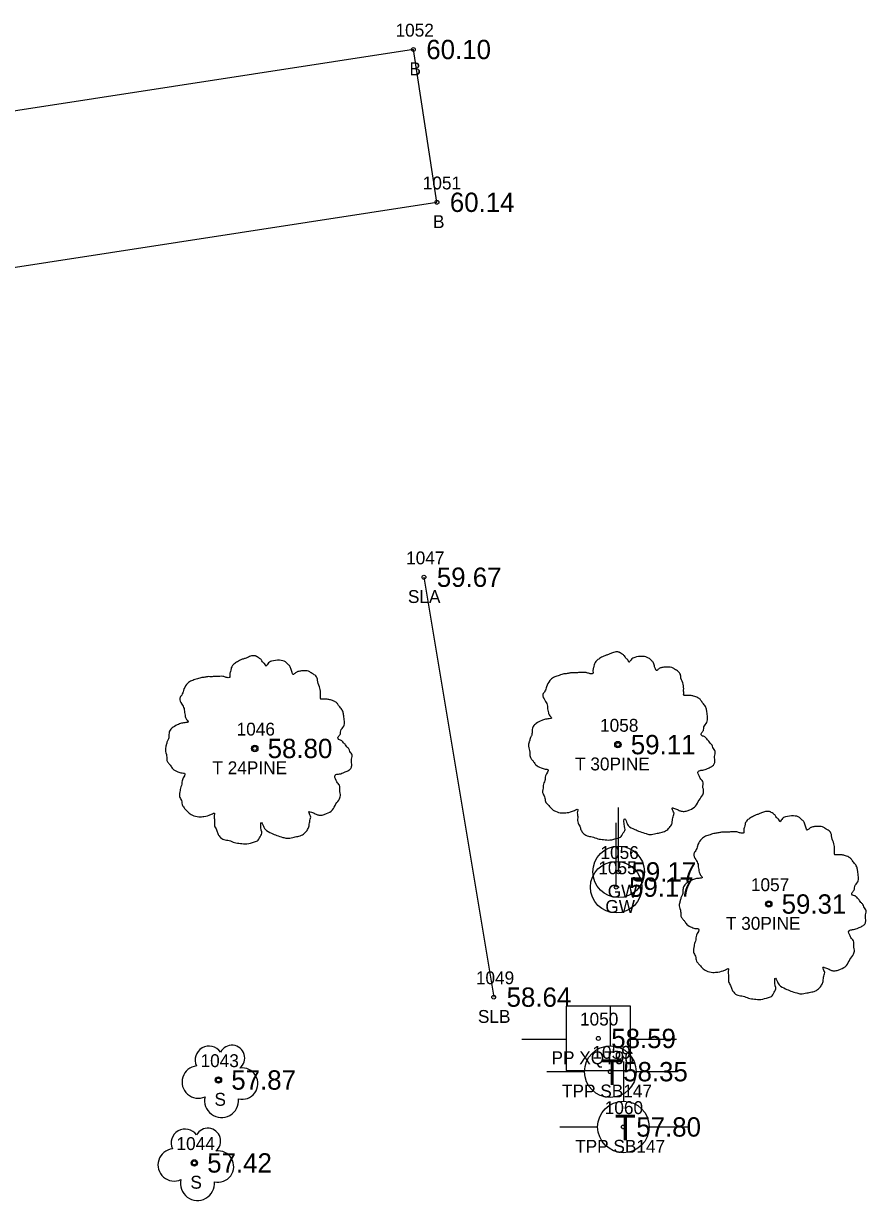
# Model space of a CAD drawing. Extents: x 2420113 to 2422887, y 845323 to 846653.
# Drawn here: x 2420530 to 2420595.4, y 845741.1 to 845832.4 of the extents above; entities that cross this region are included whole.
import ezdxf

# ---------------------------------------------------------------- set-up
doc = ezdxf.new("R2010")
doc.units = 0
for name, color, linetype in [('RD_EX_Bldg', 7, 'Continuous'), ('RD_EX_Bldg_txCode', 7, 'Continuous'), ('RD_EX_TX_Bldg_ELEV', 7, 'Continuous'), ('RD_EX_TX_UT_ELEV', 7, 'Continuous'), ('RD_EX_TX_VEG_ELEV', 7, 'Continuous'), ('RD_EX_UT', 7, 'Continuous'), ('RD_EX_UT_txCode', 7, 'Continuous'), ('RD_EX_VEG', 7, 'Continuous'), ('RD_EX_VEG_txCode', 7, 'Continuous'), ('RD_HC_Survey_ELEV', 7, 'Continuous'), ('RD_SMD_Locator', 7, 'Continuous')]:
    doc.layers.add(name, color=color, linetype=linetype)

msp = doc.modelspace()

# ---------------------------------------------------------------- linework, layer by layer
at = {"layer": 'RD_EX_Bldg'}
msp.add_lwpolyline([(2420506.493, 845809.989), (2420562.053, 845818.556), (2420560.224, 845830.416), (2420504.664, 845821.849), (2420506.493, 845809.989)], dxfattribs=at)
at = {"layer": 'RD_EX_UT'}
for p, q in [((2420576.152, 845766.583), (2420576.152, 845771.583)), ((2420575.962, 845765.398), (2420575.962, 845770.398)), ((2420577.071, 845756.164), (2420572.071, 845756.164)), ((2420572.071, 845756.164), (2420572.071, 845751.164)), ((2420575.504, 845756.144), (2420575.504, 845753.074)), ((2420577.071, 845751.164), (2420577.071, 845756.164)), ((2420568.64, 845753.602), (2420572.109, 845753.602)), ((2420577, 845753.602), (2420580.64, 845753.602)), ((2420576.524, 845751.853), (2420576.524, 845748.783)), ((2420570.574, 845751.089), (2420573.504, 845751.089)), ((2420572.071, 845751.164), (2420577.071, 845751.164)), ((2420577.504, 845751.089), (2420580.574, 845751.089)), ((2420571.594, 845746.798), (2420574.524, 845746.798)), ((2420578.524, 845746.798), (2420581.594, 845746.798))]:
    msp.add_line(p, q, dxfattribs=at)
for centre, radius in [((2420576.152, 845766.583), 1.999), ((2420575.962, 845765.398), 1.999), ((2420575.504, 845751.074), 2), ((2420576.524, 845746.783), 2)]:
    msp.add_circle(centre, radius, dxfattribs=at)
at = {"layer": 'RD_EX_VEG'}
msp.add_line((2420561.044, 845789.453), (2420566.458, 845756.86), dxfattribs=at)
for centre, radius in [((2420547.912, 845776.163), 0.25), ((2420576.097, 845776.46), 0.25), ((2420576.084, 845776.441), 0.0001), ((2420547.899, 845776.144), 0.0001), ((2420587.804, 845764.087), 0.25), ((2420587.792, 845764.068), 0.0001), ((2420545.09, 845750.427), 0.25), ((2420543.222, 845743.991), 0.25)]:
    msp.add_circle(centre, radius, dxfattribs=at)
for centre, radius, start, end in [((2420544.369, 845751.974), 1.084, 34.97629, 204.75602), ((2420546.135, 845752.129), 0.995, 308.76261, 152.04674), ((2420543.526, 845750.271), 1.257, 96.45179, 294.73401), ((2420546.93, 845750.147), 1.218, 256.56668, 98.10463), ((2420545.336, 845748.83), 1.318, 166.88266, 5.75893), ((2420542.501, 845745.538), 1.084, 34.97629, 204.75602), ((2420544.267, 845745.693), 0.995, 308.76261, 152.04674), ((2420541.658, 845743.836), 1.257, 96.45179, 294.73401), ((2420545.061, 845743.712), 1.218, 256.56668, 98.10463), ((2420543.467, 845742.395), 1.318, 166.88266, 5.75893)]:
    msp.add_arc(centre, radius, start, end, dxfattribs=at)
for points in [[(2420576.229, 845783.627), (2420575.929, 845783.652), (2420575.604, 845783.552), (2420575.354, 845783.452), (2420575.129, 845783.377), (2420574.904, 845783.277), (2420574.604, 845783.102), (2420574.379, 845782.902), (2420574.254, 845782.652), (2420574.204, 845782.427), (2420574.154, 845782.152), (2420574.154, 845781.977), (2420574.03, 845781.952), (2420573.88, 845781.977), (2420573.63, 845782.052), (2420573.38, 845782.052), (2420573.13, 845782.052), (2420572.78, 845782.027), (2420572.43, 845782.027), (2420572.155, 845781.977), (2420571.83, 845781.928), (2420571.456, 845781.803), (2420571.106, 845781.678), (2420570.806, 845781.428), (2420570.556, 845780.953), (2420570.431, 845780.603), (2420570.281, 845780.353), (2420570.431, 845779.903), (2420570.606, 845779.554), (2420570.631, 845779.354), (2420570.706, 845778.929), (2420570.806, 845778.704), (2420570.931, 845778.504), (2420570.856, 845778.479), (2420570.481, 845778.429), (2420570.181, 845778.329), (2420569.756, 845778.104), (2420569.531, 845777.879), (2420569.431, 845777.554), (2420569.407, 845777.205), (2420569.307, 845777.005), (2420569.232, 845776.73), (2420569.207, 845776.655), (2420569.157, 845776.33), (2420569.257, 845775.88), (2420569.282, 845775.53), (2420569.407, 845775.305), (2420569.556, 845775.131), (2420569.731, 845774.881), (2420570.131, 845774.656), (2420570.456, 845774.556), (2420570.656, 845774.531), (2420570.481, 845774.031), (2420570.431, 845773.681), (2420570.306, 845773.281), (2420570.306, 845773.206), (2420570.256, 845772.732), (2420570.406, 845772.407), (2420570.481, 845772.032), (2420570.656, 845771.807), (2420570.931, 845771.507), (2420571.256, 845771.282), (2420571.756, 845771.157), (2420572.155, 845771.182), (2420572.73, 845771.357), (2420572.98, 845771.432), (2420572.955, 845771.257), (2420572.98, 845770.882), (2420572.98, 845770.458), (2420573.13, 845770.133), (2420573.23, 845769.858), (2420573.38, 845769.608), (2420573.705, 845769.383), (2420574.104, 845769.308), (2420574.529, 845769.158), (2420574.979, 845769.083), (2420575.479, 845769.058), (2420576.079, 845769.208), (2420576.353, 845769.333), (2420576.453, 845769.508), (2420576.653, 845769.883), (2420576.603, 845770.108), (2420576.628, 845770.707), (2420576.728, 845770.532), (2420576.903, 845770.183), (2420577.403, 845769.883), (2420577.803, 845769.708), (2420578.278, 845769.558), (2420578.578, 845769.483), (2420579.052, 845769.558), (2420579.427, 845769.633), (2420579.802, 845769.758), (2420580.102, 845770.033), (2420580.277, 845770.308), (2420580.327, 845770.582), (2420580.402, 845770.957), (2420580.452, 845771.132)], [(2420580.452, 845771.132), (2420580.377, 845771.307), (2420580.327, 845771.557), (2420580.402, 845771.532), (2420580.577, 845771.482), (2420580.852, 845771.357), (2420581.076, 845771.282), (2420581.401, 845771.307), (2420581.676, 845771.407), (2420582.126, 845771.682), (2420582.401, 845772.157), (2420582.676, 845772.557), (2420582.751, 845772.881), (2420582.701, 845773.106), (2420582.676, 845773.606), (2420582.476, 845773.856), (2420582.426, 845773.981), (2420582.326, 845774.381), (2420582.401, 845774.431), (2420582.676, 845774.481), (2420583.051, 845774.606), (2420583.325, 845774.731), (2420583.55, 845774.906), (2420583.625, 845775.131), (2420583.6, 845775.53), (2420583.65, 845775.93), (2420583.575, 845776.08), (2420583.475, 845776.23), (2420583.4, 845776.43), (2420583.25, 845776.58), (2420583.151, 845776.73), (2420583.051, 845776.83), (2420582.926, 845776.98), (2420582.751, 845777.105), (2420582.601, 845777.155), (2420582.551, 845777.305), (2420582.701, 845777.504), (2420582.751, 845777.604), (2420582.776, 845777.829), (2420583.001, 845778.179), (2420583.051, 845778.579), (2420583.001, 845779.004), (2420582.951, 845779.279), (2420582.801, 845779.554), (2420582.601, 845779.803), (2420582.476, 845779.978), (2420582.301, 845780.103), (2420581.976, 845780.228), (2420581.726, 845780.278), (2420581.376, 845780.278), (2420581.176, 845780.328), (2420581.201, 845780.378), (2420581.201, 845780.528), (2420581.201, 845780.803), (2420581.126, 845781.253), (2420580.976, 845781.753), (2420580.976, 845781.778), (2420580.876, 845782.027), (2420580.652, 845782.227), (2420580.477, 845782.327), (2420580.277, 845782.452), (2420580.027, 845782.477), (2420579.727, 845782.477), (2420579.452, 845782.427), (2420579.252, 845782.327), (2420579.077, 845782.202), (2420579.002, 845782.352), (2420578.902, 845782.652), (2420578.852, 845782.802), (2420578.702, 845782.977), (2420578.478, 845783.177), (2420578.028, 845783.302), (2420577.403, 845783.227), (2420577.103, 845783.027), (2420576.953, 845782.852), (2420576.903, 845782.977), (2420576.703, 845783.177), (2420576.603, 845783.352), (2420576.428, 845783.477), (2420576.279, 845783.577), (2420576.179, 845783.627)], [(2420548.044, 845783.33), (2420547.744, 845783.355), (2420547.419, 845783.255), (2420547.169, 845783.156), (2420546.944, 845783.081), (2420546.719, 845782.981), (2420546.419, 845782.806), (2420546.194, 845782.606), (2420546.069, 845782.356), (2420546.019, 845782.131), (2420545.969, 845781.856), (2420545.969, 845781.681), (2420545.845, 845781.656), (2420545.695, 845781.681), (2420545.445, 845781.756), (2420545.195, 845781.756), (2420544.945, 845781.756), (2420544.595, 845781.731), (2420544.245, 845781.731), (2420543.97, 845781.681), (2420543.645, 845781.631), (2420543.271, 845781.506), (2420542.921, 845781.381), (2420542.621, 845781.131), (2420542.371, 845780.657), (2420542.246, 845780.307), (2420542.096, 845780.057), (2420542.246, 845779.607), (2420542.421, 845779.257), (2420542.446, 845779.057), (2420542.521, 845778.633), (2420542.621, 845778.408), (2420542.746, 845778.208), (2420542.671, 845778.183), (2420542.296, 845778.133), (2420541.996, 845778.033), (2420541.571, 845777.808), (2420541.346, 845777.583), (2420541.246, 845777.258), (2420541.222, 845776.908), (2420541.122, 845776.708), (2420541.047, 845776.433), (2420541.022, 845776.358), (2420540.972, 845776.034), (2420541.072, 845775.584), (2420541.097, 845775.234), (2420541.222, 845775.009), (2420541.371, 845774.834), (2420541.546, 845774.584), (2420541.946, 845774.359), (2420542.271, 845774.259), (2420542.471, 845774.234), (2420542.296, 845773.735), (2420542.246, 845773.385), (2420542.121, 845772.985), (2420542.121, 845772.91), (2420542.071, 845772.435), (2420542.221, 845772.11), (2420542.296, 845771.736), (2420542.471, 845771.511), (2420542.746, 845771.211), (2420543.071, 845770.986), (2420543.571, 845770.861), (2420543.97, 845770.886), (2420544.545, 845771.061), (2420544.795, 845771.136), (2420544.77, 845770.961), (2420544.795, 845770.586), (2420544.795, 845770.161), (2420544.945, 845769.836), (2420545.045, 845769.561), (2420545.195, 845769.312), (2420545.52, 845769.087), (2420545.919, 845769.012), (2420546.344, 845768.862), (2420546.794, 845768.787), (2420547.294, 845768.762), (2420547.894, 845768.912), (2420548.168, 845769.037), (2420548.268, 845769.212), (2420548.468, 845769.586), (2420548.418, 845769.811), (2420548.443, 845770.411), (2420548.543, 845770.236), (2420548.718, 845769.886), (2420549.218, 845769.586), (2420549.618, 845769.412), (2420550.093, 845769.262), (2420550.393, 845769.187), (2420550.867, 845769.262), (2420551.242, 845769.337), (2420551.617, 845769.462), (2420551.917, 845769.736), (2420552.092, 845770.011), (2420552.142, 845770.286), (2420552.217, 845770.661), (2420552.267, 845770.836)], [(2420552.267, 845770.836), (2420552.192, 845771.011), (2420552.142, 845771.261), (2420552.217, 845771.236), (2420552.392, 845771.186), (2420552.667, 845771.061), (2420552.891, 845770.986), (2420553.216, 845771.011), (2420553.491, 845771.111), (2420553.941, 845771.386), (2420554.216, 845771.86), (2420554.491, 845772.26), (2420554.566, 845772.585), (2420554.516, 845772.81), (2420554.491, 845773.31), (2420554.291, 845773.56), (2420554.241, 845773.685), (2420554.141, 845774.084), (2420554.216, 845774.134), (2420554.491, 845774.184), (2420554.866, 845774.309), (2420555.14, 845774.434), (2420555.365, 845774.609), (2420555.44, 845774.834), (2420555.415, 845775.234), (2420555.465, 845775.634), (2420555.39, 845775.784), (2420555.29, 845775.934), (2420555.215, 845776.134), (2420555.065, 845776.283), (2420554.966, 845776.433), (2420554.866, 845776.533), (2420554.741, 845776.683), (2420554.566, 845776.808), (2420554.416, 845776.858), (2420554.366, 845777.008), (2420554.516, 845777.208), (2420554.566, 845777.308), (2420554.591, 845777.533), (2420554.816, 845777.883), (2420554.866, 845778.283), (2420554.816, 845778.707), (2420554.766, 845778.982), (2420554.616, 845779.257), (2420554.416, 845779.507), (2420554.291, 845779.682), (2420554.116, 845779.807), (2420553.791, 845779.932), (2420553.541, 845779.982), (2420553.191, 845779.982), (2420552.991, 845780.032), (2420553.016, 845780.082), (2420553.016, 845780.232), (2420553.016, 845780.507), (2420552.941, 845780.956), (2420552.791, 845781.456), (2420552.791, 845781.481), (2420552.691, 845781.731), (2420552.467, 845781.931), (2420552.292, 845782.031), (2420552.092, 845782.156), (2420551.842, 845782.181), (2420551.542, 845782.181), (2420551.267, 845782.131), (2420551.067, 845782.031), (2420550.892, 845781.906), (2420550.817, 845782.056), (2420550.717, 845782.356), (2420550.667, 845782.506), (2420550.517, 845782.681), (2420550.293, 845782.881), (2420549.843, 845783.006), (2420549.218, 845782.931), (2420548.918, 845782.731), (2420548.768, 845782.556), (2420548.718, 845782.681), (2420548.518, 845782.881), (2420548.418, 845783.056), (2420548.243, 845783.181), (2420548.094, 845783.28), (2420547.994, 845783.33)], [(2420587.936, 845771.254), (2420587.636, 845771.279), (2420587.311, 845771.179), (2420587.061, 845771.079), (2420586.837, 845771.004), (2420586.612, 845770.904), (2420586.312, 845770.729), (2420586.087, 845770.529), (2420585.962, 845770.279), (2420585.912, 845770.054), (2420585.862, 845769.779), (2420585.862, 845769.604), (2420585.737, 845769.579), (2420585.587, 845769.604), (2420585.337, 845769.679), (2420585.087, 845769.679), (2420584.837, 845769.679), (2420584.488, 845769.654), (2420584.138, 845769.654), (2420583.863, 845769.604), (2420583.538, 845769.555), (2420583.163, 845769.43), (2420582.813, 845769.305), (2420582.513, 845769.055), (2420582.264, 845768.58), (2420582.139, 845768.23), (2420581.989, 845767.98), (2420582.139, 845767.53), (2420582.314, 845767.181), (2420582.338, 845766.981), (2420582.413, 845766.556), (2420582.513, 845766.331), (2420582.638, 845766.131), (2420582.563, 845766.106), (2420582.189, 845766.056), (2420581.889, 845765.956), (2420581.464, 845765.731), (2420581.239, 845765.506), (2420581.139, 845765.181), (2420581.114, 845764.832), (2420581.014, 845764.632), (2420580.939, 845764.357), (2420580.914, 845764.282), (2420580.864, 845763.957), (2420580.964, 845763.507), (2420580.989, 845763.157), (2420581.114, 845762.932), (2420581.264, 845762.758), (2420581.439, 845762.508), (2420581.839, 845762.283), (2420582.164, 845762.183), (2420582.363, 845762.158), (2420582.189, 845761.658), (2420582.139, 845761.308), (2420582.014, 845760.908), (2420582.014, 845760.833), (2420581.964, 845760.359), (2420582.114, 845760.034), (2420582.189, 845759.659), (2420582.363, 845759.434), (2420582.638, 845759.134), (2420582.963, 845758.909), (2420583.463, 845758.784), (2420583.863, 845758.809), (2420584.438, 845758.984), (2420584.687, 845759.059), (2420584.662, 845758.884), (2420584.687, 845758.509), (2420584.687, 845758.085), (2420584.837, 845757.76), (2420584.937, 845757.485), (2420585.087, 845757.235), (2420585.412, 845757.01), (2420585.812, 845756.935), (2420586.237, 845756.785), (2420586.687, 845756.71), (2420587.186, 845756.685), (2420587.786, 845756.835), (2420588.061, 845756.96), (2420588.161, 845757.135), (2420588.361, 845757.51), (2420588.311, 845757.735), (2420588.336, 845758.334), (2420588.436, 845758.159), (2420588.611, 845757.81), (2420589.111, 845757.51), (2420589.51, 845757.335), (2420589.985, 845757.185), (2420590.285, 845757.11), (2420590.76, 845757.185), (2420591.135, 845757.26), (2420591.509, 845757.385), (2420591.809, 845757.66), (2420591.984, 845757.935), (2420592.034, 845758.209), (2420592.109, 845758.584), (2420592.159, 845758.759)], [(2420592.159, 845758.759), (2420592.084, 845758.934), (2420592.034, 845759.184), (2420592.109, 845759.159), (2420592.284, 845759.109), (2420592.559, 845758.984), (2420592.784, 845758.909), (2420593.109, 845758.934), (2420593.384, 845759.034), (2420593.833, 845759.309), (2420594.108, 845759.784), (2420594.383, 845760.184), (2420594.458, 845760.508), (2420594.408, 845760.733), (2420594.383, 845761.233), (2420594.183, 845761.483), (2420594.133, 845761.608), (2420594.033, 845762.008), (2420594.108, 845762.058), (2420594.383, 845762.108), (2420594.758, 845762.233), (2420595.033, 845762.358), (2420595.258, 845762.533), (2420595.333, 845762.758), (2420595.308, 845763.157), (2420595.358, 845763.557), (2420595.283, 845763.707), (2420595.183, 845763.857), (2420595.108, 845764.057), (2420594.958, 845764.207), (2420594.858, 845764.357), (2420594.758, 845764.457), (2420594.633, 845764.607), (2420594.458, 845764.732), (2420594.308, 845764.782), (2420594.258, 845764.932), (2420594.408, 845765.131), (2420594.458, 845765.231), (2420594.483, 845765.456), (2420594.708, 845765.806), (2420594.758, 845766.206), (2420594.708, 845766.631), (2420594.658, 845766.906), (2420594.508, 845767.181), (2420594.308, 845767.43), (2420594.183, 845767.605), (2420594.008, 845767.73), (2420593.684, 845767.855), (2420593.434, 845767.905), (2420593.084, 845767.905), (2420592.884, 845767.955), (2420592.909, 845768.005), (2420592.909, 845768.155), (2420592.909, 845768.43), (2420592.834, 845768.88), (2420592.684, 845769.38), (2420592.684, 845769.405), (2420592.584, 845769.654), (2420592.359, 845769.854), (2420592.184, 845769.954), (2420591.984, 845770.079), (2420591.734, 845770.104), (2420591.435, 845770.104), (2420591.16, 845770.054), (2420590.96, 845769.954), (2420590.785, 845769.829), (2420590.71, 845769.979), (2420590.61, 845770.279), (2420590.56, 845770.429), (2420590.41, 845770.604), (2420590.185, 845770.804), (2420589.735, 845770.929), (2420589.111, 845770.854), (2420588.811, 845770.654), (2420588.661, 845770.479), (2420588.611, 845770.604), (2420588.411, 845770.804), (2420588.311, 845770.979), (2420588.136, 845771.104), (2420587.986, 845771.204), (2420587.886, 845771.254)]]:
    msp.add_spline(points, degree=3, dxfattribs=at)
at = {"layer": 'RD_SMD_Locator'}
for centre in [(2420560.224, 845830.416), (2420562.053, 845818.556), (2420561.044, 845789.453), (2420547.912, 845776.163), (2420576.097, 845776.46), (2420576.152, 845766.583), (2420575.962, 845765.398), (2420587.804, 845764.087), (2420566.458, 845756.86), (2420574.58, 845753.655), (2420575.504, 845751.074), (2420545.09, 845750.427), (2420576.524, 845746.783), (2420543.222, 845743.991)]:
    msp.add_circle(centre, 0.15, dxfattribs=at)

# ---------------------------------------------------------------- texts
at = {"layer": 'RD_EX_Bldg_txCode'}
for s, p in [('1052', (2420558.838, 845831.416)), ('B', (2420559.917, 845828.416)), ('1051', (2420560.951, 845819.556)), ('B', (2420561.746, 845816.556))]:
    msp.add_text(s, height=1, dxfattribs=at).set_placement(p)
at = {"layer": 'RD_EX_TX_Bldg_ELEV'}
for s, p in [('60.10', (2420561.224, 845829.666)), ('60.14', (2420563.053, 845817.806))]:
    msp.add_text(s, height=1.5, dxfattribs=at).set_placement(p)
at = {"layer": 'RD_EX_TX_UT_ELEV'}
for s, p in [('59.17', (2420577.152, 845765.833)), ('59.17', (2420576.962, 845764.648)), ('58.35', (2420576.504, 845750.324)), ('57.80', (2420577.524, 845746.033))]:
    msp.add_text(s, height=1.5, dxfattribs=at).set_placement(p)
at = {"layer": 'RD_EX_TX_VEG_ELEV'}
for s, p in [('59.67', (2420562.044, 845788.703)), ('59.11', (2420577.097, 845775.71)), ('58.80', (2420548.912, 845775.413)), ('59.31', (2420588.804, 845763.337)), ('58.64', (2420567.458, 845756.11)), ('57.87', (2420546.09, 845749.677)), ('57.42', (2420544.222, 845743.241))]:
    msp.add_text(s, height=1.5, dxfattribs=at).set_placement(p)
at = {"layer": 'RD_EX_UT'}
for p in [(2420574.835, 845750.027), (2420575.855, 845745.735)]:
    msp.add_text('T', height=2, dxfattribs=at).set_placement(p)
at = {"layer": 'RD_EX_UT_txCode'}
for s, p in [('1056', (2420574.743, 845767.583)), ('1055', (2420574.576, 845766.398)), ('GW', (2420575.309, 845764.583)), ('GW', (2420575.12, 845763.398)), ('1050', (2420573.155, 845754.655)), ('PP XQT96', (2420570.943, 845751.655)), ('1059', (2420574.118, 845752.074)), ('TPP SB147', (2420571.756, 845749.074)), ('1060', (2420575.075, 845747.783)), ('TPP SB147', (2420572.776, 845744.783))]:
    msp.add_text(s, height=1, dxfattribs=at).set_placement(p)
at = {"layer": 'RD_EX_VEG_txCode'}
for s, p in [('1047', (2420559.658, 845790.453)), ('SLA', (2420559.799, 845787.453)), ('1046', (2420546.502, 845777.163)), ('1058', (2420574.711, 845777.46)), ('T 30PINE', (2420572.77, 845774.46)), ('T 24PINE', (2420544.624, 845774.163)), ('1057', (2420586.418, 845765.087)), ('T 30PINE', (2420584.477, 845762.087)), ('1049', (2420565.073, 845757.86)), ('SLB', (2420565.23, 845754.86)), ('1043', (2420543.704, 845751.427)), ('S', (2420544.783, 845748.427)), ('1044', (2420541.836, 845744.991)), ('S', (2420542.915, 845741.991))]:
    msp.add_text(s, height=1, dxfattribs=at).set_placement(p)
at = {"layer": 'RD_HC_Survey_ELEV'}
msp.add_text('58.59', height=1.5, dxfattribs=at).set_placement((2420575.58, 845752.905))

doc.saveas('drawing.dxf')
